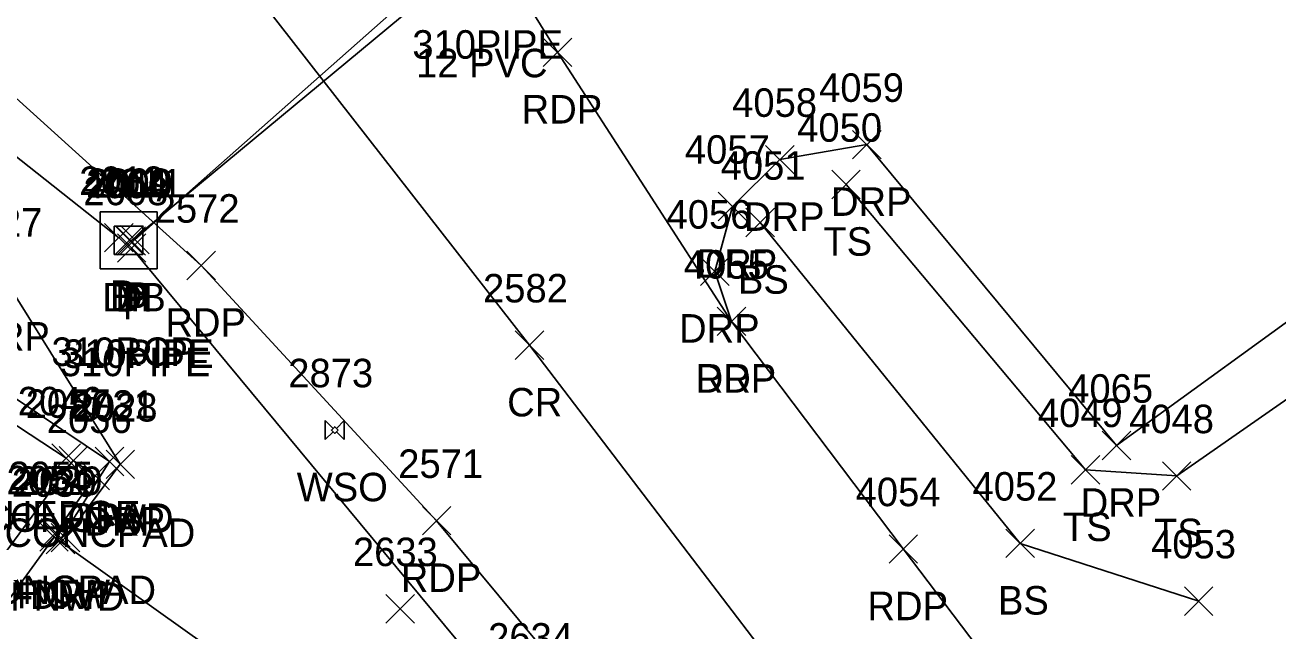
# Model space of a CAD drawing. Extents: x 1634209 to 1639641, y 608564 to 612258.
# Drawn here: x 1639153.3 to 1639241.2, y 611186.4 to 611228.9 of the extents above; entities that cross this region are included whole.
import ezdxf

# ---------------------------------------------------------------- set-up
doc = ezdxf.new("R2010")
doc.units = 0
for name, color, linetype in [('D_A', 7, 'Continuous'), ('D_C', 7, 'Continuous'), ('D_I', 7, 'Continuous'), ('D_TIC', 7, 'Continuous'), ('DCP', 7, 'Continuous'), ('DS', 7, 'Continuous'), ('L_A', 7, 'Continuous'), ('L_I', 7, 'Continuous'), ('L_TIC', 7, 'Continuous'), ('LAHR', 7, 'Continuous'), ('LBC', 7, 'Continuous'), ('LELB', 7, 'Continuous'), ('LFNC', 7, 'Continuous'), ('LS', 7, 'Continuous'), ('P_A', 7, 'Continuous'), ('P_I', 7, 'Continuous'), ('P_TIC', 7, 'Continuous'), ('PET', 7, 'Continuous'), ('PRC', 7, 'Continuous'), ('R_A', 7, 'Continuous'), ('R_I', 7, 'Continuous'), ('R_TIC', 7, 'Continuous'), ('RDP', 7, 'Continuous'), ('U_A', 7, 'Continuous'), ('U_I', 7, 'Continuous'), ('UWV', 7, 'Continuous')]:
    doc.layers.add(name, color=color, linetype=linetype)

msp = doc.modelspace()

# ---------------------------------------------------------------- linework, layer by layer
at = {"layer": 'D_TIC'}
for points in [[(1639158.896, 611212.983), (1639160.896, 611214.983)], [(1639160.896, 611212.983), (1639158.896, 611214.983)], [(1639159.635, 611212.808), (1639161.635, 611214.808)], [(1639161.635, 611212.808), (1639159.635, 611214.808)], [(1639160.026, 611212.845), (1639162.026, 611214.845)], [(1639162.026, 611212.845), (1639160.026, 611214.845)], [(1639159.772, 611212.757), (1639161.772, 611214.757)], [(1639161.772, 611212.757), (1639159.772, 611214.757)], [(1639159.798, 611212.264), (1639161.798, 611214.264)], [(1639161.798, 611212.264), (1639159.798, 611214.264)]]:
    msp.add_lwpolyline(points, dxfattribs=at)
at = {"layer": 'DCP'}
for points in [[(1639185.519, 611235.547), (1639161.026, 611213.845)], [(1639185.409, 611234.243), (1639160.772, 611213.757)], [(1639159.896, 611213.983), (1639135.4, 611233.388)], [(1639280.744, 611068.51), (1639160.798, 611213.264)]]:
    msp.add_lwpolyline(points, dxfattribs=at)
at = {"layer": 'DS'}
for p, q in [((1639158.585, 611215.803), (1639162.585, 611215.803)), ((1639158.585, 611211.803), (1639158.585, 611215.803)), ((1639162.585, 611215.803), (1639162.585, 611211.803)), ((1639159.585, 611212.803), (1639159.585, 611214.803)), ((1639159.585, 611214.803), (1639161.585, 611214.803)), ((1639161.585, 611214.803), (1639161.585, 611212.803)), ((1639160.59, 611213.804), (1639160.59, 611213.804)), ((1639160.59, 611213.804), (1639160.59, 611213.804)), ((1639161.585, 611212.803), (1639159.585, 611212.803)), ((1639162.585, 611211.803), (1639158.585, 611211.803))]:
    msp.add_line(p, q, dxfattribs=at)
at = {"layer": 'L_TIC'}
for points in [[(1639209.891, 611216.719), (1639211.891, 611218.719)], [(1639211.891, 611216.719), (1639209.891, 611218.719)], [(1639203.868, 611214.051), (1639205.868, 611216.051)], [(1639205.868, 611214.051), (1639203.868, 611216.051)], [(1639155.206, 611197.515), (1639157.206, 611199.515)], [(1639157.206, 611197.515), (1639155.206, 611199.515)], [(1639155.707, 611197.34), (1639157.707, 611199.34)], [(1639157.707, 611197.34), (1639155.707, 611199.34)], [(1639158.249, 611197.276), (1639160.249, 611199.276)], [(1639160.249, 611197.276), (1639158.249, 611199.276)], [(1639157.243, 611196.277), (1639159.243, 611198.277)], [(1639159.243, 611196.277), (1639157.243, 611198.277)], [(1639226.685, 611196.691), (1639228.685, 611198.691)], [(1639228.685, 611196.691), (1639226.685, 611198.691)], [(1639233.075, 611196.263), (1639235.075, 611198.263)], [(1639235.075, 611196.263), (1639233.075, 611198.263)], [(1639154.358, 611191.972), (1639156.358, 611193.972)], [(1639156.358, 611191.972), (1639154.358, 611193.972)], [(1639154.49, 611192.268), (1639156.49, 611194.268)], [(1639156.49, 611192.268), (1639154.49, 611194.268)], [(1639154.815, 611191.801), (1639156.815, 611193.801)], [(1639156.815, 611191.801), (1639154.815, 611193.801)], [(1639222.098, 611191.533), (1639224.098, 611193.533)], [(1639224.098, 611191.533), (1639222.098, 611193.533)], [(1639234.618, 611187.476), (1639236.618, 611189.476)], [(1639236.618, 611187.476), (1639234.618, 611189.476)], [(1639178.622, 611186.935), (1639180.622, 611188.935)], [(1639180.622, 611186.935), (1639178.622, 611188.935)]]:
    msp.add_lwpolyline(points, dxfattribs=at)
at = {"layer": 'LAHR'}
msp.add_lwpolyline([(1639113.651, 611204.037), (1639123.989, 611219.711), (1639156.206, 611198.515)], dxfattribs=at)
at = {"layer": 'LBC'}
msp.add_lwpolyline([(1639184.889, 611171.787), (1639182.528, 611173.659), (1639182.278, 611173.787), (1639155.358, 611192.972), (1639133.903, 611163.404)], dxfattribs=at)
at = {"layer": 'LELB'}
for points in [[(1639266.996, 611220.227), (1639234.075, 611197.263), (1639227.685, 611197.691), (1639210.891, 611217.719)], [(1639204.868, 611215.051), (1639223.098, 611192.533), (1639235.618, 611188.476)]]:
    msp.add_lwpolyline(points, dxfattribs=at)
at = {"layer": 'LFNC'}
msp.add_lwpolyline([(1639155.815, 611192.801), (1639159.249, 611198.276), (1639123.947, 611221.972), (1639112.019, 611204.198)], dxfattribs=at)
at = {"layer": 'LS'}
msp.add_lwpolyline([(1639155.49, 611193.268), (1639158.243, 611197.277), (1639156.707, 611198.34), (1639144.983, 611182.462)], dxfattribs=at)
at = {"layer": 'P_TIC'}
for points in [[(1639189.658, 611225.999), (1639191.658, 611227.999)], [(1639191.658, 611225.999), (1639189.658, 611227.999)], [(1639164.678, 611211.038), (1639166.678, 611213.038)], [(1639166.678, 611211.038), (1639164.678, 611213.038)], [(1639201.86, 611207.109), (1639203.86, 611209.109)], [(1639203.86, 611207.109), (1639201.86, 611209.109)], [(1639187.697, 611205.44), (1639189.697, 611207.44)], [(1639189.697, 611205.44), (1639187.697, 611207.44)], [(1639181.184, 611193.122), (1639183.184, 611195.122)], [(1639183.184, 611193.122), (1639181.184, 611195.122)], [(1639213.901, 611191.139), (1639215.901, 611193.139)], [(1639215.901, 611191.139), (1639213.901, 611193.139)]]:
    msp.add_lwpolyline(points, dxfattribs=at)
at = {"layer": 'PET'}
for points in [[(1639227.993, 611172.983), (1639228.322, 611174.392), (1639214.901, 611192.139), (1639202.86, 611208.109), (1639190.658, 611226.999), (1639183.077, 611239.215), (1639162.79, 611271.004), (1639160.915, 611274.858), (1639160.063, 611279.394), (1639160.107, 611285.354), (1639161.856, 611291.074), (1639181.022, 611319.858), (1639203.193, 611353.293), (1639219.74, 611378.248), (1639229.459, 611393.468), (1639239.186, 611407.624), (1639252.485, 611428.758), (1639267.876, 611454.496), (1639285.596, 611485.313)], [(1639410.825, 610892.364), (1639390.458, 610919.541), (1639371.801, 610946.358), (1639349.879, 610975.696), (1639327.189, 611005.386), (1639302.754, 611038.38), (1639275.028, 611075.512), (1639248.834, 611108.817), (1639223.626, 611142.441), (1639205.296, 611166.276), (1639182.184, 611194.122), (1639165.678, 611212.038), (1639150.219, 611225.989), (1639136.405, 611234.042), (1639135.28, 611232.533), (1639130.918, 611235.275), (1639127.562, 611237.663), (1639124.139, 611238.638)]]:
    msp.add_lwpolyline(points, dxfattribs=at)
at = {"layer": 'PRC'}
msp.add_lwpolyline([(1639145.026, 611260.3), (1639159.742, 611243.634), (1639188.697, 611206.44), (1639218.548, 611167.285), (1639245.48, 611130.825), (1639271.83, 611094.919), (1639293.449, 611066.846), (1639319.074, 611033.054), (1639349.486, 610993.068), (1639374.145, 610959.599), (1639396.768, 610928.589), (1639419.083, 610897.866)], dxfattribs=at)
at = {"layer": 'R_TIC'}
for points in [[(1639211.346, 611219.517), (1639213.346, 611221.517)], [(1639213.346, 611219.517), (1639211.346, 611221.517)], [(1639205.244, 611218.465), (1639207.244, 611220.465)], [(1639207.244, 611218.465), (1639205.244, 611220.465)], [(1639201.931, 611215.175), (1639203.931, 611217.175)], [(1639203.931, 611215.175), (1639201.931, 611217.175)], [(1639200.695, 611210.62), (1639202.695, 611212.62)], [(1639202.695, 611210.62), (1639200.695, 611212.62)], [(1639201.86, 611207.109), (1639203.86, 611209.109)], [(1639203.86, 611207.109), (1639201.86, 611209.109)], [(1639228.854, 611198.402), (1639230.854, 611200.402)], [(1639230.854, 611198.402), (1639228.854, 611200.402)], [(1639159.002, 611197.081), (1639161.002, 611199.081)], [(1639161.002, 611197.081), (1639159.002, 611199.081)], [(1639155.164, 611191.928), (1639157.164, 611193.928)], [(1639157.164, 611191.928), (1639155.164, 611193.928)]]:
    msp.add_lwpolyline(points, dxfattribs=at)
at = {"layer": 'RDP'}
for points in [[(1639149.147, 611223.119), (1639151.93, 611211.062), (1639160.002, 611198.081), (1639156.164, 611192.928)], [(1639202.86, 611208.109), (1639201.695, 611211.62), (1639202.931, 611216.175), (1639206.244, 611219.465), (1639212.346, 611220.517), (1639229.854, 611199.402), (1639245.263, 611210.575), (1639262.11, 611223.36)]]:
    msp.add_lwpolyline(points, dxfattribs=at)
at = {"layer": 'UWV'}
for p, q in [((1639174.376, 611201.151), (1639174.925, 611200.602)), ((1639175.71, 611201.151), (1639175.161, 611200.602)), ((1639174.925, 611200.367), (1639174.376, 611199.818)), ((1639175.161, 611200.367), (1639175.71, 611199.818))]:
    msp.add_line(p, q, dxfattribs=at)
for points in [[(1639174.376, 611201.151), (1639174.376, 611199.818)], [(1639175.71, 611199.818), (1639175.71, 611201.151)]]:
    msp.add_lwpolyline(points, dxfattribs=at)
msp.add_lwpolyline([(1639175.279, 611200.485), (1639175.043, 611200.72), (1639174.807, 611200.485), (1639175.043, 611200.249)], close=True, dxfattribs=at)

# ---------------------------------------------------------------- texts
at = {"layer": 'D_A'}
for s, p in [('DIB', (1639158.738, 611208.808)), ('P', (1639159.274, 611208.983)), ('DI', (1639159.645, 611208.804)), ('P', (1639160.15, 611208.757)), ('P', (1639160.404, 611208.845)), ('P', (1639160.176, 611208.264))]:
    msp.add_text(s, height=2, dxfattribs=at).set_placement(p)
at = {"layer": 'D_C'}
for s, p in [('310PIPE', (1639180.48, 611226.547)), ('12 PVC', (1639180.74, 611225.243)), ('310RCP', (1639155.18, 611204.983)), ('310PIPE', (1639155.759, 611204.264)), ('310PIPE', (1639155.987, 611204.845))]:
    msp.add_text(s, height=2, dxfattribs=at).set_placement(p)
at = {"layer": 'D_I'}
for s, p in [('2012', (1639157.125, 611216.983)), ('4064', (1639157.386, 611216.757)), ('2009', (1639157.601, 611216.845)), ('2010', (1639157.732, 611216.804)), ('2011', (1639158.431, 611216.808)), ('2608', (1639157.412, 611216.264))]:
    msp.add_text(s, height=2, dxfattribs=at).set_placement(p)
at = {"layer": 'L_A'}
for s, p in [('TS', (1639209.3, 611212.719)), ('BS', (1639203.309, 611210.051)), ('HEDGE', (1639151.907, 611193.515)), ('CONCPAD', (1639150.353, 611193.34)), ('FNWD', (1639155.714, 611193.276)), ('TS', (1639226.095, 611192.691)), ('CONCPAD', (1639151.889, 611192.277)), ('TS', (1639232.484, 611192.263)), ('CONCPAD', (1639149.136, 611188.268)), ('FNWD', (1639152.279, 611187.801)), ('HOW', (1639152.744, 611187.972)), ('BS', (1639221.539, 611187.533))]:
    msp.add_text(s, height=2, dxfattribs=at).set_placement(p)
at = {"layer": 'L_I'}
for s, p in [('4050', (1639207.466, 611220.719)), ('4051', (1639202.097, 611218.051)), ('2046', (1639152.813, 611201.515)), ('2057', (1639153.369, 611201.34)), ('2031', (1639156.478, 611201.276)), ('4049', (1639224.339, 611200.691)), ('2056', (1639154.849, 611200.277)), ('4048', (1639230.736, 611200.263)), ('2055', (1639152.152, 611196.268)), ('2054', (1639152.02, 611195.972)), ('2030', (1639152.39, 611195.801)), ('4052', (1639219.76, 611195.533)), ('2633', (1639176.315, 611190.935)), ('4053', (1639232.279, 611191.476)), ('2634', (1639185.796, 611184.932))]:
    msp.add_text(s, height=2, dxfattribs=at).set_placement(p)
at = {"layer": 'P_A'}
for s, p in [('RDP', (1639188.146, 611221.999)), ('RDP', (1639163.166, 611207.038)), ('RDP', (1639200.348, 611203.109)), ('CR', (1639187.13, 611201.44)), ('RDP', (1639179.672, 611189.122)), ('RDP', (1639212.39, 611187.139))]:
    msp.add_text(s, height=2, dxfattribs=at).set_placement(p)
at = {"layer": 'P_I'}
for s, p in [('2572', (1639162.418, 611215.038)), ('4055', (1639199.522, 611211.109)), ('2582', (1639185.437, 611209.44)), ('2571', (1639179.491, 611197.122)), ('4054', (1639211.563, 611195.139))]:
    msp.add_text(s, height=2, dxfattribs=at).set_placement(p)
at = {"layer": 'R_A'}
for p in [(1639209.834, 611215.517), (1639203.733, 611214.465), (1639200.419, 611211.175), (1639149.418, 611206.062), (1639199.183, 611206.62), (1639200.348, 611203.109), (1639227.342, 611194.402), (1639157.49, 611193.081), (1639153.652, 611187.928)]:
    msp.add_text('DRP', height=2, dxfattribs=at).set_placement(p)
at = {"layer": 'R_I'}
for s, p in [('4059', (1639209, 611223.517)), ('4058', (1639202.906, 611222.465)), ('4057', (1639199.592, 611219.175)), ('4056', (1639198.301, 611214.62)), ('2027', (1639148.591, 611214.062)), ('4055', (1639199.522, 611211.109)), ('4065', (1639226.468, 611202.402)), ('2028', (1639156.664, 611201.081)), ('2029', (1639152.818, 611195.928))]:
    msp.add_text(s, height=2, dxfattribs=at).set_placement(p)
at = {"layer": 'U_A'}
msp.add_text('WSO', height=2, dxfattribs=at).set_placement((1639172.374, 611195.485))
at = {"layer": 'U_I'}
msp.add_text('2873', height=2, dxfattribs=at).set_placement((1639171.783, 611203.485))

doc.saveas('drawing.dxf')
